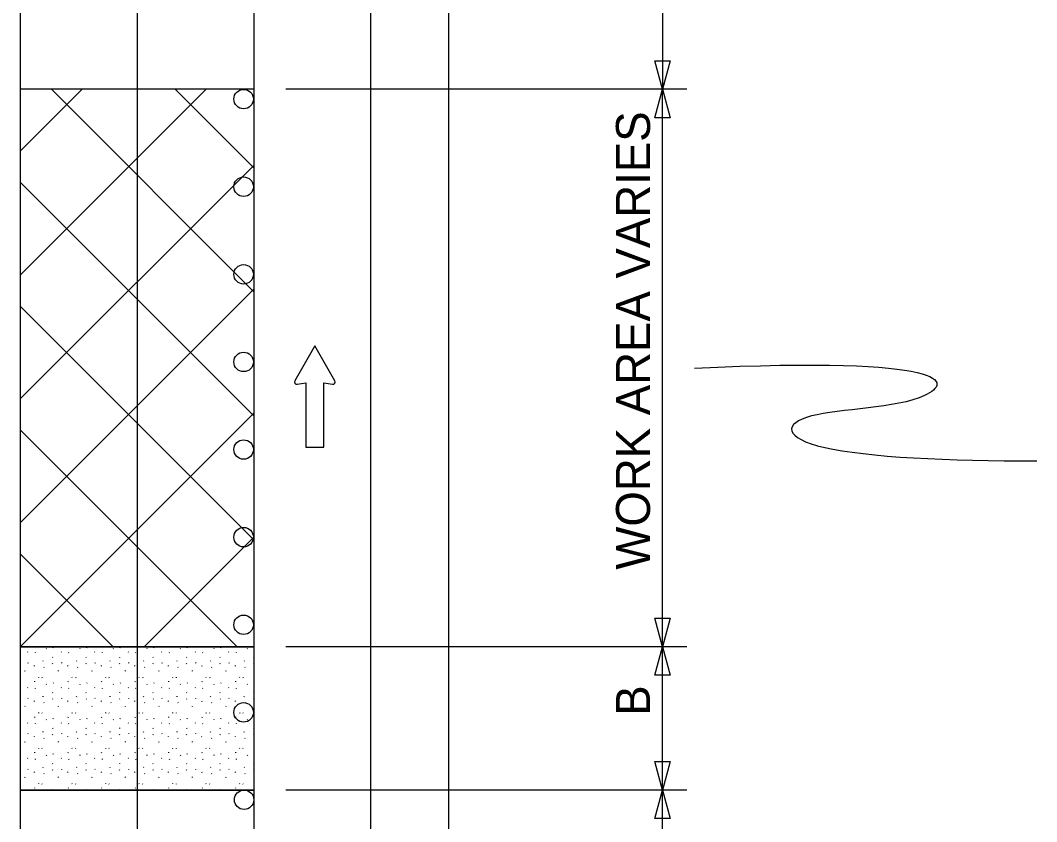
# Model space of a CAD drawing. Extents: x 16727 to 18475, y 5729 to 6909.
# Drawn here: x 16917.2 to 17126.1, y 6552.5 to 6717.1 of the extents above; entities that cross this region are included whole.
import ezdxf

# ---------------------------------------------------------------- set-up
doc = ezdxf.new("R2010")
doc.units = 0
for name, color, linetype in [('ALI_LEGAL_EX', 7, 'Continuous'), ('MT_SCRATCH_LEVEL_A', 7, 'Continuous'), ('MT_SCRATCH_LEVEL_E', 7, 'Continuous'), ('PAVT_EDGE_EX', 7, 'Continuous'), ('TRAFFIC_SIGNS_PR', 7, 'Continuous'), ('TYPICAL_TEXT_DIMEN_PR', 7, 'Continuous')]:
    doc.layers.add(name, color=color, linetype=linetype)

msp = doc.modelspace()

# ---------------------------------------------------------------- linework, layer by layer
at = {"layer": 'ALI_LEGAL_EX'}
for p, q in [((16941.23, 6891.16), (16941.23, 6061.98)), ((16965.23, 6891.16), (16965.23, 6061.98)), ((16965.23, 6891.16), (16965.23, 6061.98))]:
    msp.add_line(p, q, dxfattribs=at)
for points in [[(16941.23, 6691.16), (16941.23, 6666.16)], [(16965.23, 6691.16), (16965.23, 6666.16)], [(16941.23, 6591.16), (16941.23, 6566.16)], [(16965.23, 6591.16), (16965.23, 6566.16)]]:
    msp.add_lwpolyline(points, dxfattribs=at)
at = {"layer": 'MT_SCRATCH_LEVEL_A'}
for p, q in [((16965.23, 6702.97), (16917.23, 6702.97)), ((16965.23, 6588.44), (16917.23, 6588.44)), ((16965.23, 6559.01), (16917.23, 6559.01))]:
    msp.add_line(p, q, dxfattribs=at)
at = {"layer": 'MT_SCRATCH_LEVEL_E'}
for p, q in [((16977.76, 6650.29), (16973.65, 6643.05)), ((16977.76, 6650.29), (16973.65, 6643.05)), ((16981.9, 6643.05), (16977.76, 6650.29)), ((16981.9, 6643.05), (16977.76, 6650.29)), ((16974.13, 6642.37), (16975.9, 6642.68)), ((16974.13, 6642.37), (16975.9, 6642.68)), ((16975.9, 6642.68), (16975.9, 6629.43)), ((16975.9, 6642.68), (16975.9, 6629.43)), ((16979.65, 6629.43), (16979.65, 6642.68)), ((16979.65, 6642.68), (16981.42, 6642.37)), ((16979.65, 6629.43), (16979.65, 6642.68)), ((16979.65, 6642.68), (16981.42, 6642.37)), ((16975.9, 6629.43), (16979.65, 6629.43)), ((16975.9, 6629.43), (16979.65, 6629.43))]:
    msp.add_line(p, q, dxfattribs=at)
for centre, start, end in [((16974.05, 6642.83), 150.4248, 279.9638), ((16974.05, 6642.83), 150.4248, 279.9638), ((16981.49, 6642.83), 260.0362, 29.7731), ((16981.49, 6642.83), 260.0362, 29.7731)]:
    msp.add_arc(centre, 0.463, start, end, dxfattribs=at)
at = {"layer": 'PAVT_EDGE_EX'}
for p, q in [((16917.23, 6891.16), (16917.23, 6061.98)), ((16917.23, 6891.16), (16917.23, 6061.98)), ((16989.23, 6891.16), (16989.23, 6061.98)), ((17005.23, 6891.16), (17005.23, 6061.98)), ((16965.23, 6702.97), (16917.23, 6702.97)), ((16917.23, 6702.97), (16917.23, 6588.44)), ((16917.23, 6690.26), (16929.94, 6702.97)), ((16917.23, 6664.8), (16955.4, 6702.97)), ((16965.23, 6661.35), (16923.61, 6702.97)), ((16965.23, 6686.81), (16949.06, 6702.97)), ((16917.23, 6639.35), (16965.23, 6687.35)), ((16965.23, 6635.9), (16917.23, 6683.9)), ((16917.23, 6613.89), (16965.23, 6661.89)), ((16965.23, 6610.44), (16917.23, 6658.44)), ((16917.23, 6588.44), (16965.23, 6636.44)), ((16961.78, 6588.44), (16917.23, 6632.98)), ((16942.69, 6588.44), (16965.23, 6610.98)), ((16936.32, 6588.44), (16917.23, 6607.53)), ((16917.23, 6588.44), (16965.23, 6588.44)), ((16965.23, 6588.44), (16917.23, 6588.44)), ((16917.23, 6588.44), (16917.23, 6559.01)), ((16917.23, 6588.44), (16917.23, 6588.44)), ((16918.73, 6587.39), (16918.78, 6587.31)), ((16920.26, 6587.25), (16920.31, 6587.17)), ((16922.55, 6588.06), (16922.6, 6587.99)), ((16924, 6588.22), (16924.05, 6588.33)), ((16925.61, 6587.39), (16925.67, 6587.31)), ((16927.15, 6587.25), (16927.2, 6587.17)), ((16929.43, 6588.06), (16929.49, 6587.99)), ((16930.88, 6588.22), (16930.94, 6588.33)), ((16932.5, 6587.39), (16932.55, 6587.31)), ((16934.03, 6587.25), (16934.08, 6587.17)), ((16936.32, 6588.06), (16936.37, 6587.99)), ((16937.77, 6588.22), (16937.82, 6588.33)), ((16939.39, 6587.39), (16939.44, 6587.31)), ((16940.92, 6587.25), (16940.97, 6587.17)), ((16943.21, 6588.06), (16943.26, 6587.99)), ((16944.66, 6588.22), (16944.71, 6588.33)), ((16946.28, 6587.39), (16946.33, 6587.31)), ((16947.81, 6587.25), (16947.86, 6587.17)), ((16950.1, 6588.06), (16950.15, 6587.99)), ((16951.55, 6588.22), (16951.6, 6588.33)), ((16953.17, 6587.39), (16953.22, 6587.31)), ((16954.69, 6587.25), (16954.75, 6587.17)), ((16956.99, 6588.06), (16957.04, 6587.99)), ((16958.43, 6588.22), (16958.49, 6588.33)), ((16960.05, 6587.39), (16960.1, 6587.31)), ((16961.58, 6587.25), (16961.63, 6587.17)), ((16963.87, 6588.06), (16963.92, 6587.99)), ((16918.78, 6585.18), (16918.83, 6585.1)), ((16921.9, 6585.46), (16921.95, 6585.57)), ((16923.82, 6586.33), (16923.88, 6586.25)), ((16925.66, 6585.18), (16925.72, 6585.1)), ((16928.79, 6585.46), (16928.84, 6585.57)), ((16930.71, 6586.33), (16930.76, 6586.25)), ((16932.55, 6585.18), (16932.6, 6585.1)), ((16935.67, 6585.46), (16935.72, 6585.57)), ((16937.6, 6586.33), (16937.65, 6586.25)), ((16939.44, 6585.18), (16939.49, 6585.1)), ((16942.56, 6585.46), (16942.61, 6585.57)), ((16944.49, 6586.33), (16944.54, 6586.25)), ((16946.33, 6585.18), (16946.38, 6585.1)), ((16949.45, 6585.46), (16949.5, 6585.57)), ((16951.37, 6586.33), (16951.43, 6586.25)), ((16953.21, 6585.18), (16953.26, 6585.1)), ((16956.34, 6585.46), (16956.39, 6585.57)), ((16958.26, 6586.33), (16958.31, 6586.25)), ((16960.1, 6585.18), (16960.15, 6585.1)), ((16963.22, 6585.46), (16963.28, 6585.57)), ((16965.15, 6586.33), (16965.2, 6586.25)), ((16918.16, 6583.42), (16918.21, 6583.54)), ((16920.06, 6584.6), (16920.07, 6584.48)), ((16922.09, 6584.26), (16922.14, 6584.18)), ((16923.87, 6584.93), (16923.92, 6585.04)), ((16925.05, 6583.42), (16925.1, 6583.54)), ((16926.94, 6584.6), (16926.96, 6584.48)), ((16928.97, 6584.26), (16929.03, 6584.18)), ((16930.75, 6584.93), (16930.81, 6585.04)), ((16931.93, 6583.42), (16931.98, 6583.54)), ((16933.83, 6584.6), (16933.85, 6584.48)), ((16935.86, 6584.26), (16935.91, 6584.18)), ((16937.64, 6584.93), (16937.69, 6585.04)), ((16938.82, 6583.42), (16938.87, 6583.54)), ((16940.72, 6584.6), (16940.73, 6584.48)), ((16942.75, 6584.26), (16942.8, 6584.18)), ((16944.53, 6584.93), (16944.58, 6585.04)), ((16945.71, 6583.42), (16945.76, 6583.54)), ((16947.61, 6584.6), (16947.62, 6584.48)), ((16949.64, 6584.26), (16949.69, 6584.18)), ((16951.42, 6584.93), (16951.47, 6585.04)), ((16952.6, 6583.42), (16952.65, 6583.54)), ((16954.49, 6584.6), (16954.51, 6584.48)), ((16956.53, 6584.26), (16956.58, 6584.18)), ((16958.3, 6584.93), (16958.36, 6585.04)), ((16959.48, 6583.42), (16959.53, 6583.54)), ((16961.38, 6584.6), (16961.4, 6584.48)), ((16963.41, 6584.26), (16963.46, 6584.18)), ((16965.19, 6584.93), (16965.23, 6585.01)), ((16920.18, 6581.23), (16920.23, 6581.34)), ((16920.94, 6582.19), (16920.99, 6582.11)), ((16921.68, 6582.16), (16921.73, 6582.08)), ((16924, 6580.93), (16924.05, 6581.05)), ((16927.06, 6581.23), (16927.12, 6581.34)), ((16927.83, 6582.19), (16927.88, 6582.11)), ((16928.57, 6582.16), (16928.62, 6582.08)), ((16930.88, 6580.93), (16930.94, 6581.05)), ((16933.95, 6581.23), (16934, 6581.34)), ((16934.72, 6582.19), (16934.77, 6582.11)), ((16935.45, 6582.16), (16935.51, 6582.08)), ((16937.77, 6580.93), (16937.82, 6581.05)), ((16940.84, 6581.23), (16940.89, 6581.34)), ((16941.6, 6582.19), (16941.65, 6582.11)), ((16942.34, 6582.16), (16942.39, 6582.08)), ((16944.66, 6580.93), (16944.71, 6581.05)), ((16947.73, 6581.23), (16947.78, 6581.34)), ((16948.49, 6582.19), (16948.54, 6582.11)), ((16949.23, 6582.16), (16949.28, 6582.08)), ((16951.55, 6580.93), (16951.6, 6581.05)), ((16954.62, 6581.23), (16954.67, 6581.34)), ((16955.38, 6582.19), (16955.43, 6582.11)), ((16956.12, 6582.16), (16956.17, 6582.08)), ((16958.43, 6580.93), (16958.49, 6581.05)), ((16961.5, 6581.23), (16961.55, 6581.34)), ((16962.27, 6582.19), (16962.32, 6582.11)), ((16963, 6582.16), (16963.06, 6582.08)), ((16918.73, 6580.1), (16918.78, 6580.02)), ((16920.26, 6579.96), (16920.31, 6579.88)), ((16922.55, 6580.78), (16922.6, 6580.7)), ((16923.82, 6579.04), (16923.88, 6578.96)), ((16925.61, 6580.1), (16925.67, 6580.02)), ((16927.15, 6579.96), (16927.2, 6579.88)), ((16929.43, 6580.78), (16929.49, 6580.7)), ((16930.71, 6579.04), (16930.76, 6578.96)), ((16932.5, 6580.1), (16932.55, 6580.02)), ((16934.03, 6579.96), (16934.08, 6579.88)), ((16936.32, 6580.78), (16936.37, 6580.7)), ((16937.6, 6579.04), (16937.65, 6578.96)), ((16939.39, 6580.1), (16939.44, 6580.02)), ((16940.92, 6579.96), (16940.97, 6579.88)), ((16943.21, 6580.78), (16943.26, 6580.7)), ((16944.49, 6579.04), (16944.54, 6578.96)), ((16946.28, 6580.1), (16946.33, 6580.02)), ((16947.81, 6579.96), (16947.86, 6579.88)), ((16950.1, 6580.78), (16950.15, 6580.7)), ((16951.37, 6579.04), (16951.43, 6578.96)), ((16953.17, 6580.1), (16953.22, 6580.02)), ((16954.69, 6579.96), (16954.75, 6579.88)), ((16956.99, 6580.78), (16957.04, 6580.7)), ((16958.26, 6579.04), (16958.31, 6578.96)), ((16960.05, 6580.1), (16960.1, 6580.02)), ((16961.58, 6579.96), (16961.63, 6579.88)), ((16963.87, 6580.78), (16963.92, 6580.7)), ((16965.15, 6579.04), (16965.2, 6578.96)), ((16918.78, 6577.89), (16918.83, 6577.81)), ((16920.06, 6577.32), (16920.07, 6577.2)), ((16921.9, 6578.17), (16921.95, 6578.29)), ((16922.09, 6576.97), (16922.14, 6576.9)), ((16923.87, 6577.64), (16923.92, 6577.76)), ((16925.66, 6577.89), (16925.72, 6577.81)), ((16926.94, 6577.32), (16926.96, 6577.2)), ((16928.79, 6578.17), (16928.84, 6578.29)), ((16928.97, 6576.97), (16929.03, 6576.9)), ((16930.75, 6577.64), (16930.81, 6577.76)), ((16932.55, 6577.89), (16932.6, 6577.81)), ((16933.83, 6577.32), (16933.85, 6577.2)), ((16935.67, 6578.17), (16935.72, 6578.29)), ((16935.86, 6576.97), (16935.91, 6576.9)), ((16937.64, 6577.64), (16937.69, 6577.76)), ((16939.44, 6577.89), (16939.49, 6577.81)), ((16940.72, 6577.32), (16940.73, 6577.2)), ((16942.56, 6578.17), (16942.61, 6578.29)), ((16942.75, 6576.97), (16942.8, 6576.9)), ((16944.53, 6577.64), (16944.58, 6577.76)), ((16946.33, 6577.89), (16946.38, 6577.81)), ((16947.61, 6577.32), (16947.62, 6577.2)), ((16949.45, 6578.17), (16949.5, 6578.29)), ((16949.64, 6576.97), (16949.69, 6576.9)), ((16951.42, 6577.64), (16951.47, 6577.76)), ((16953.21, 6577.89), (16953.26, 6577.81)), ((16954.49, 6577.32), (16954.51, 6577.2)), ((16956.34, 6578.17), (16956.39, 6578.29)), ((16956.53, 6576.97), (16956.58, 6576.9)), ((16958.3, 6577.64), (16958.36, 6577.76)), ((16960.1, 6577.89), (16960.15, 6577.81)), ((16961.38, 6577.32), (16961.4, 6577.2)), ((16963.22, 6578.17), (16963.28, 6578.29)), ((16963.41, 6576.97), (16963.46, 6576.9)), ((16965.19, 6577.64), (16965.23, 6577.73)), ((16918.16, 6576.14), (16918.21, 6576.26)), ((16920.94, 6574.9), (16920.99, 6574.82)), ((16921.68, 6574.87), (16921.73, 6574.8)), ((16925.05, 6576.14), (16925.1, 6576.26)), ((16927.83, 6574.9), (16927.88, 6574.82)), ((16928.57, 6574.87), (16928.62, 6574.8)), ((16931.93, 6576.14), (16931.98, 6576.26)), ((16934.72, 6574.9), (16934.77, 6574.82)), ((16935.45, 6574.87), (16935.51, 6574.8)), ((16938.82, 6576.14), (16938.87, 6576.26)), ((16941.6, 6574.9), (16941.65, 6574.82)), ((16942.34, 6574.87), (16942.39, 6574.8)), ((16945.71, 6576.14), (16945.76, 6576.26)), ((16948.49, 6574.9), (16948.54, 6574.82)), ((16949.23, 6574.87), (16949.28, 6574.8)), ((16952.6, 6576.14), (16952.65, 6576.26)), ((16955.38, 6574.9), (16955.43, 6574.82)), ((16956.12, 6574.87), (16956.17, 6574.8)), ((16959.48, 6576.14), (16959.53, 6576.26)), ((16962.27, 6574.9), (16962.32, 6574.82)), ((16963, 6574.87), (16963.06, 6574.8)), ((16918.73, 6572.82), (16918.78, 6572.74)), ((16920.18, 6573.94), (16920.23, 6574.06)), ((16920.26, 6572.68), (16920.31, 6572.6)), ((16922.55, 6573.49), (16922.6, 6573.42)), ((16924, 6573.65), (16924.05, 6573.76)), ((16925.61, 6572.82), (16925.67, 6572.74)), ((16927.06, 6573.94), (16927.12, 6574.06)), ((16927.15, 6572.68), (16927.2, 6572.6)), ((16929.43, 6573.49), (16929.49, 6573.42)), ((16930.88, 6573.65), (16930.94, 6573.76)), ((16932.5, 6572.82), (16932.55, 6572.74)), ((16933.95, 6573.94), (16934, 6574.06)), ((16934.03, 6572.68), (16934.08, 6572.6)), ((16936.32, 6573.49), (16936.37, 6573.42)), ((16937.77, 6573.65), (16937.82, 6573.76)), ((16939.39, 6572.82), (16939.44, 6572.74)), ((16940.84, 6573.94), (16940.89, 6574.06)), ((16940.92, 6572.68), (16940.97, 6572.6)), ((16943.21, 6573.49), (16943.26, 6573.42)), ((16944.66, 6573.65), (16944.71, 6573.76)), ((16946.28, 6572.82), (16946.33, 6572.74)), ((16947.73, 6573.94), (16947.78, 6574.06)), ((16947.81, 6572.68), (16947.86, 6572.6)), ((16950.1, 6573.49), (16950.15, 6573.42)), ((16951.55, 6573.65), (16951.6, 6573.76)), ((16953.17, 6572.82), (16953.22, 6572.74)), ((16954.62, 6573.94), (16954.67, 6574.06)), ((16954.69, 6572.68), (16954.75, 6572.6)), ((16956.99, 6573.49), (16957.04, 6573.42)), ((16958.43, 6573.65), (16958.49, 6573.76)), ((16960.05, 6572.82), (16960.1, 6572.74)), ((16961.5, 6573.94), (16961.55, 6574.06)), ((16961.58, 6572.68), (16961.63, 6572.6)), ((16963.87, 6573.49), (16963.92, 6573.42)), ((16918.78, 6570.61), (16918.83, 6570.53)), ((16921.9, 6570.89), (16921.95, 6571)), ((16923.82, 6571.76), (16923.88, 6571.68)), ((16925.66, 6570.61), (16925.72, 6570.53)), ((16928.79, 6570.89), (16928.84, 6571)), ((16930.71, 6571.76), (16930.76, 6571.68)), ((16932.55, 6570.61), (16932.6, 6570.53)), ((16935.67, 6570.89), (16935.72, 6571)), ((16937.6, 6571.76), (16937.65, 6571.68)), ((16939.44, 6570.61), (16939.49, 6570.53)), ((16942.56, 6570.89), (16942.61, 6571)), ((16944.49, 6571.76), (16944.54, 6571.68)), ((16946.33, 6570.61), (16946.38, 6570.53)), ((16949.45, 6570.89), (16949.5, 6571)), ((16951.37, 6571.76), (16951.43, 6571.68)), ((16953.21, 6570.61), (16953.26, 6570.53)), ((16956.34, 6570.89), (16956.39, 6571)), ((16958.26, 6571.76), (16958.31, 6571.68)), ((16960.1, 6570.61), (16960.15, 6570.53)), ((16963.22, 6570.89), (16963.28, 6571)), ((16965.15, 6571.76), (16965.2, 6571.68)), ((16918.16, 6568.85), (16918.21, 6568.97)), ((16920.06, 6570.03), (16920.07, 6569.91)), ((16922.09, 6569.69), (16922.14, 6569.61)), ((16923.87, 6570.36), (16923.92, 6570.47)), ((16925.05, 6568.85), (16925.1, 6568.97)), ((16926.94, 6570.03), (16926.96, 6569.91)), ((16928.97, 6569.69), (16929.03, 6569.61)), ((16930.75, 6570.36), (16930.81, 6570.47)), ((16931.93, 6568.85), (16931.98, 6568.97)), ((16933.83, 6570.03), (16933.85, 6569.91)), ((16935.86, 6569.69), (16935.91, 6569.61)), ((16937.64, 6570.36), (16937.69, 6570.47)), ((16938.82, 6568.85), (16938.87, 6568.97)), ((16940.72, 6570.03), (16940.73, 6569.91)), ((16942.75, 6569.69), (16942.8, 6569.61)), ((16944.53, 6570.36), (16944.58, 6570.47)), ((16945.71, 6568.85), (16945.76, 6568.97)), ((16947.61, 6570.03), (16947.62, 6569.91)), ((16949.64, 6569.69), (16949.69, 6569.61)), ((16951.42, 6570.36), (16951.47, 6570.47)), ((16952.6, 6568.85), (16952.65, 6568.97)), ((16954.49, 6570.03), (16954.51, 6569.91)), ((16956.53, 6569.69), (16956.58, 6569.61)), ((16958.3, 6570.36), (16958.36, 6570.47)), ((16959.48, 6568.85), (16959.53, 6568.97)), ((16961.38, 6570.03), (16961.4, 6569.91)), ((16963.41, 6569.69), (16963.46, 6569.61)), ((16965.19, 6570.36), (16965.23, 6570.44)), ((16920.18, 6566.66), (16920.23, 6566.77)), ((16920.94, 6567.62), (16920.99, 6567.54)), ((16921.68, 6567.59), (16921.73, 6567.51)), ((16924, 6566.36), (16924.05, 6566.48)), ((16927.06, 6566.66), (16927.12, 6566.77)), ((16927.83, 6567.62), (16927.88, 6567.54)), ((16928.57, 6567.59), (16928.62, 6567.51)), ((16930.88, 6566.36), (16930.94, 6566.48)), ((16933.95, 6566.66), (16934, 6566.77)), ((16934.72, 6567.62), (16934.77, 6567.54)), ((16935.45, 6567.59), (16935.51, 6567.51)), ((16937.77, 6566.36), (16937.82, 6566.48)), ((16940.84, 6566.66), (16940.89, 6566.77)), ((16941.6, 6567.62), (16941.65, 6567.54)), ((16942.34, 6567.59), (16942.39, 6567.51)), ((16944.66, 6566.36), (16944.71, 6566.48)), ((16947.73, 6566.66), (16947.78, 6566.77)), ((16948.49, 6567.62), (16948.54, 6567.54)), ((16949.23, 6567.59), (16949.28, 6567.51)), ((16951.55, 6566.36), (16951.6, 6566.48)), ((16954.62, 6566.66), (16954.67, 6566.77)), ((16955.38, 6567.62), (16955.43, 6567.54)), ((16956.12, 6567.59), (16956.17, 6567.51)), ((16958.43, 6566.36), (16958.49, 6566.48)), ((16961.5, 6566.66), (16961.55, 6566.77)), ((16962.27, 6567.62), (16962.32, 6567.54)), ((16963, 6567.59), (16963.06, 6567.51)), ((16918.73, 6565.53), (16918.78, 6565.45)), ((16920.26, 6565.39), (16920.31, 6565.31)), ((16922.55, 6566.21), (16922.6, 6566.13)), ((16923.82, 6564.47), (16923.88, 6564.39)), ((16925.61, 6565.53), (16925.67, 6565.45)), ((16927.15, 6565.39), (16927.2, 6565.31)), ((16929.43, 6566.21), (16929.49, 6566.13)), ((16930.71, 6564.47), (16930.76, 6564.39)), ((16932.5, 6565.53), (16932.55, 6565.45)), ((16934.03, 6565.39), (16934.08, 6565.31)), ((16936.32, 6566.21), (16936.37, 6566.13)), ((16937.6, 6564.47), (16937.65, 6564.39)), ((16939.39, 6565.53), (16939.44, 6565.45)), ((16940.92, 6565.39), (16940.97, 6565.31)), ((16943.21, 6566.21), (16943.26, 6566.13)), ((16944.49, 6564.47), (16944.54, 6564.39)), ((16946.28, 6565.53), (16946.33, 6565.45)), ((16947.81, 6565.39), (16947.86, 6565.31)), ((16950.1, 6566.21), (16950.15, 6566.13)), ((16951.37, 6564.47), (16951.43, 6564.39)), ((16953.17, 6565.53), (16953.22, 6565.45)), ((16954.69, 6565.39), (16954.75, 6565.31)), ((16956.99, 6566.21), (16957.04, 6566.13)), ((16958.26, 6564.47), (16958.31, 6564.39)), ((16960.05, 6565.53), (16960.1, 6565.45)), ((16961.58, 6565.39), (16961.63, 6565.31)), ((16963.87, 6566.21), (16963.92, 6566.13)), ((16965.15, 6564.47), (16965.2, 6564.39)), ((16918.78, 6563.32), (16918.83, 6563.24)), ((16920.06, 6562.75), (16920.07, 6562.63)), ((16921.9, 6563.6), (16921.95, 6563.72)), ((16922.09, 6562.4), (16922.14, 6562.32)), ((16923.87, 6563.07), (16923.92, 6563.19)), ((16925.66, 6563.32), (16925.72, 6563.24)), ((16926.94, 6562.75), (16926.96, 6562.63)), ((16928.79, 6563.6), (16928.84, 6563.72)), ((16928.97, 6562.4), (16929.03, 6562.32)), ((16930.75, 6563.07), (16930.81, 6563.19)), ((16932.55, 6563.32), (16932.6, 6563.24)), ((16933.83, 6562.75), (16933.85, 6562.63)), ((16935.67, 6563.6), (16935.72, 6563.72)), ((16935.86, 6562.4), (16935.91, 6562.32)), ((16937.64, 6563.07), (16937.69, 6563.19)), ((16939.44, 6563.32), (16939.49, 6563.24)), ((16940.72, 6562.75), (16940.73, 6562.63)), ((16942.56, 6563.6), (16942.61, 6563.72)), ((16942.75, 6562.4), (16942.8, 6562.32)), ((16944.53, 6563.07), (16944.58, 6563.19)), ((16946.33, 6563.32), (16946.38, 6563.24)), ((16947.61, 6562.75), (16947.62, 6562.63)), ((16949.45, 6563.6), (16949.5, 6563.72)), ((16949.64, 6562.4), (16949.69, 6562.32)), ((16951.42, 6563.07), (16951.47, 6563.19)), ((16953.21, 6563.32), (16953.26, 6563.24)), ((16954.49, 6562.75), (16954.51, 6562.63)), ((16956.34, 6563.6), (16956.39, 6563.72)), ((16956.53, 6562.4), (16956.58, 6562.32)), ((16958.3, 6563.07), (16958.36, 6563.19)), ((16960.1, 6563.32), (16960.15, 6563.24)), ((16961.38, 6562.75), (16961.4, 6562.63)), ((16963.22, 6563.6), (16963.28, 6563.72)), ((16963.41, 6562.4), (16963.46, 6562.32)), ((16965.19, 6563.07), (16965.23, 6563.16)), ((16918.16, 6561.57), (16918.21, 6561.69)), ((16920.94, 6560.33), (16920.99, 6560.26)), ((16921.68, 6560.3), (16921.73, 6560.23)), ((16925.05, 6561.57), (16925.1, 6561.69)), ((16927.83, 6560.33), (16927.88, 6560.26)), ((16928.57, 6560.3), (16928.62, 6560.23)), ((16931.93, 6561.57), (16931.98, 6561.69)), ((16934.72, 6560.33), (16934.77, 6560.26)), ((16935.45, 6560.3), (16935.51, 6560.23)), ((16938.82, 6561.57), (16938.87, 6561.69)), ((16941.6, 6560.33), (16941.65, 6560.26)), ((16942.34, 6560.3), (16942.39, 6560.23)), ((16945.71, 6561.57), (16945.76, 6561.69)), ((16948.49, 6560.33), (16948.54, 6560.26)), ((16949.23, 6560.3), (16949.28, 6560.23)), ((16952.6, 6561.57), (16952.65, 6561.69)), ((16955.38, 6560.33), (16955.43, 6560.26)), ((16956.12, 6560.3), (16956.17, 6560.23)), ((16959.48, 6561.57), (16959.53, 6561.69)), ((16962.27, 6560.33), (16962.32, 6560.26)), ((16963, 6560.3), (16963.06, 6560.23)), ((16917.23, 6559.01), (16965.23, 6559.01)), ((16920.18, 6559.37), (16920.23, 6559.49)), ((16924, 6559.07), (16924.05, 6559.19)), ((16927.06, 6559.37), (16927.12, 6559.49)), ((16930.88, 6559.07), (16930.94, 6559.19)), ((16933.95, 6559.37), (16934, 6559.49)), ((16937.77, 6559.07), (16937.82, 6559.19)), ((16940.84, 6559.37), (16940.89, 6559.49)), ((16944.66, 6559.07), (16944.71, 6559.19)), ((16947.73, 6559.37), (16947.78, 6559.49)), ((16951.55, 6559.07), (16951.6, 6559.19)), ((16954.62, 6559.37), (16954.67, 6559.49)), ((16958.43, 6559.07), (16958.49, 6559.19)), ((16961.5, 6559.37), (16961.55, 6559.49))]:
    msp.add_line(p, q, dxfattribs=at)
at = {"layer": 'TRAFFIC_SIGNS_PR'}
for centre in [(16963.13, 6700.96), (16963.13, 6682.96), (16963.13, 6664.96), (16963.13, 6646.96), (16963.13, 6628.96), (16963.13, 6610.96), (16963.13, 6592.96), (16963.13, 6574.96), (16963.23, 6557.01)]:
    msp.add_circle(centre, 2, dxfattribs=at)
at = {"layer": 'TYPICAL_TEXT_DIMEN_PR'}
for p, q in [((17049.23, 6752.97), (17049.23, 6702.97)), ((17049.23, 6702.97), (17047.66, 6708.83)), ((17047.66, 6708.83), (17049.23, 6708.83)), ((17049.23, 6708.83), (17050.8, 6708.83)), ((17050.8, 6708.83), (17049.23, 6702.97)), ((17054.23, 6702.97), (16971.83, 6702.97)), ((17047.66, 6697.11), (17049.23, 6702.97)), ((17049.23, 6588.44), (17049.23, 6702.97)), ((17049.23, 6702.97), (17050.8, 6697.11)), ((17049.23, 6697.11), (17047.66, 6697.11)), ((17050.8, 6697.11), (17049.23, 6697.11)), ((17049.23, 6588.44), (17047.66, 6594.3)), ((17047.66, 6594.3), (17049.23, 6594.3)), ((17049.23, 6594.3), (17050.8, 6594.3)), ((17050.8, 6594.3), (17049.23, 6588.44)), ((17054.23, 6588.44), (16971.83, 6588.44)), ((17047.66, 6582.57), (17049.23, 6588.44)), ((17049.23, 6559.01), (17049.23, 6588.44)), ((17049.23, 6588.44), (17050.8, 6582.57)), ((17049.23, 6582.57), (17047.66, 6582.57)), ((17050.8, 6582.57), (17049.23, 6582.57)), ((17049.23, 6559.01), (17047.66, 6564.87)), ((17047.66, 6564.87), (17049.23, 6564.87)), ((17049.23, 6564.87), (17050.8, 6564.87)), ((17050.8, 6564.87), (17049.23, 6559.01)), ((17054.23, 6559.01), (16971.83, 6559.01)), ((17047.66, 6553.15), (17049.23, 6559.01)), ((17049.23, 6528.44), (17049.23, 6559.01)), ((17049.23, 6559.01), (17050.8, 6553.15)), ((17049.23, 6553.15), (17047.66, 6553.15)), ((17050.8, 6553.15), (17049.23, 6553.15))]:
    msp.add_line(p, q, dxfattribs=at)
msp.add_open_spline([(17055.8, 6645.7), (17108.94, 6648.12), (17108.94, 6637.36), (17074.02, 6637.36), (17074.02, 6628.31), (17108.23, 6626.55), (17126.15, 6626.64)], degree=3, dxfattribs=at)

# ---------------------------------------------------------------- texts
for s, p in [('WORK AREA VARIES', (17046.67, 6604.29)), ('B', (17046.67, 6574.27))]:
    msp.add_text(s, height=7, rotation=90, dxfattribs=at).set_placement(p)

doc.saveas('drawing.dxf')
